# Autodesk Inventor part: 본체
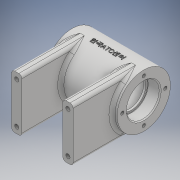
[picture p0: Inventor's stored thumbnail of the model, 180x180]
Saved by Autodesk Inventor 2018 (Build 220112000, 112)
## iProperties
Created: 2020-07
Part Number: 본체
Material: Generic
Document SubType Name: Modeling
Designer: Administrator
Density: 1 g/cm^3
Appearance: Default
Author: Administrator
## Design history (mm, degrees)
sketch "Sketch1"
  geometry: L1 (0, 26)-(-35, 26); L2 (0, 26)-(35, 26); L3 (-35, 26)-(-35, 16); L4 (-35, 16)-(-23.3, 16); L5 (-23, 15.7)-(-23, 14); L6 (-23, 14)-(-21, 14); L7 (-21, 14)-(-21, 18); L8 (-18, 21)-(18, 21); L9 (21, 18)-(21, 14); L10 (21, 14)-(23, 14); L11 (23, 14)-(23, 15.7); L12 (23.3, 16)-(35, 16); L13 (35, 16)-(35, 26); L14 (-35, 0)-(35, 0); A1 r 0.3 centre (-23.3, 15.7) between (-23, 15.7) and (-23.3, 16); A2 r 0.3 centre (23.3, 15.7) between (23.3, 16) and (23, 15.7); A3 r 3 centre (18, 18) between (21, 18) and (18, 21); A4 r 3 centre (-18, 18) between (-18, 21) and (-21, 18); 5 further points
  constraints: 28 end point, 9 perpendicular, 8 point on circle, 8 point on line, 8 tangent, 4 centre point, 2 equal radius, 2 horizontal, 2 vertical
  dimensions: "d1" = 35 distance of L1.start L1.end; "d2" = 35 distance of L1.start L2.end; "d3" = 10 distance of L1.end L3.end; "d4" = 12 distance of L3.end point (-23, 16); "d5" = 2 distance of point (-23, 16) L5.end; "d6" = 2 distance of L5.end L6.end; "d7" = 7 distance of L6.end point (-21, 21); "d8" = 42 distance of point (-21, 21) point (21, 21); "d9" = 7 distance of point (21, 21) L9.end; "d10" = 2 distance of L9.end L10.end; "d11" = 2 distance of L10.end point (23, 16); "d12" = 12 distance of point (23, 16) L12.end; "d13" = 0.3 radius of A1; "d14" = 3 radius of A3
revolve "Revolution1" sketch "Sketch1" stored, may be unused: angle "d15" = 90 deg
sketch "Sketch2"
  geometry: L1 (0, 23.558)-(0, 29); L2 (0, 29)-(5, 29); L3 (0, 23.558)-(5, 23.558); L4 (5, 23.558)-(5, 29); 1 further point
  constraints: 8 end point, 2 horizontal, 1 perpendicular, 1 vertical
  dimensions: "d18" = 5.442 distance of L1.start L1.end; "d19" = 5 distance of L1.end L2.end
revolve "Revolution2" sketch "Sketch2" stored, may be unused: angle "d20" = 90 deg
sketch "Sketch3"
  geometry: 2 further points
  constraints: 1 coincident
hole "Hole1" sketch "Sketch3" at (0, 0) diameter "d21" = 5.188; stored, may be unused: countersink angle "d25" = 90 deg, drill point angle "d27" = 118 deg; dims "d22" = 16, "d23" = 4, "d24" = 2, "d26" = 16
fillet "Fillet1" dims "d28" = 2
sketch "Sketch4"
  geometry: L1 (0, 0)-(-56.537, -20.578); L2 (0, 0)-(-32.45, 0); L3 (-21.871, -7.961)-(-19.819, -13.599); L4 (-19.819, -13.599)-(-25.199, -15.557); L5 (-25.199, -15.557)-(-27.251, -9.919); C1 r 26 at (0, 0) reference
  constraints: 10 end point, 2 perpendicular, 2 point on line, 1 horizontal, 1 parallel
  dimensions: "d31" = 20 deg angle of L2 L1; "d32" = 29 distance from line of L1.start L5; "d33" = 12 diameter of L4 L1; "d34" = 5.72494 distance between parallel lines of L3 L5; "d35" = 17.09868 distance from line of L2.end L4; "d36" = 20.57767 distance from line of L1.end L2
revolve "Revolution3" sketch "Sketch4" stored, may be unused: angle "d37" = 90 deg
sketch "Sketch5"
  geometry: 2 further points
  constraints: 1 coincident
hole "Hole2" sketch "Sketch5" at (0, 0) diameter "d38" = 5.188; stored, may be unused: countersink angle "d42" = 90 deg, drill point angle "d44" = 118 deg; dims "d39" = 16, "d40" = 4, "d41" = 2, "d43" = 16
fillet "Fillet2" dims "d45" = 2
workplane "Work Plane1"
sketch "Sketch6"
  geometry: L1 (0, 26)-(-64, 26); L2 (0, -26)-(-64, -26); L3 (-64, 26)-(-64, -26); A1 r 26 centre (0, 0) between (0, 26) and (0, -26) reference; 1 further point
  constraints: 6 end point, 2 horizontal, 2 point on circle, 2 tangent
  dimensions: "d49" = 64 distance of L1.start L1.end; "d50" = 64 distance of L2.start L2.end
extrude "Extrusion1" join sketch "Sketch6" stored distance "d51" = 10; taper "d52" = 0 deg
mirror "Mirror1"
fillet "Fillet3" dims "d53" = 3
sketch "Sketch7"
  geometry: 5 further points
hole "Hole3" sketch "Sketch7" at (0, 21), (-21, 0), (0, -21), (21, 0) diameter "d55" = 3.242; stored, may be unused: countersink angle "d59" = 90 deg, drill point angle "d61" = 118 deg; dims "d56" = 8, "d57" = 4, "d58" = 2, "d60" = 10
mirror "Mirror2"
sketch "Sketch8"
  geometry: L1 (-3, 49)-(-3, 3) reference; L2 (47, 49)-(47, 3) reference; 5 further points
hole "Hole4" sketch "Sketch8" at (2, 46), (2, 6), (52, 46), (52, 6) diameter "d68" = 4.134; stored, may be unused: countersink angle "d72" = 90 deg, drill point angle "d74" = 118 deg; dims "d69" = 8, "d70" = 4, "d71" = 2, "d73" = 10
workplane "Work Plane2"
sketch "Sketch9"
  geometry: L1 (35, -26)-(35, 26) reference; L2 (-35, -26)-(-35, 26) reference; 2 further points
  constraints: 1 other
  dimensions: "d76" = 35 distance from line of point (0, 0) L2 (derived); "d77" = 26 vertical distance of point (0, 0) L2.end (derived)
emboss "Emboss1" sketch "Sketch9" dims "d1" = 35, "d2" = 35, "d3" = 10, "d4" = 12, "d5" = 2, "d6" = 2, "d7" = 7, "d8" = 42, "d9" = 7, "d10" = 2, "d11" = 2, "d12" = 12, "d13" = 0.3, "d14" = 3, "d78" = 0.5, "d79" = 0
chamfer "Chamfer1" distance "d80" = 1; stored, may be unused: second distance "d81" = 2, angle "d82" = 45 deg
chamfer "Chamfer2" distance "d83" = 1; stored, may be unused: second distance "d84" = 2, angle "d85" = 45 deg
body "Solid1"
other parameters: "d46" = 25, "d75" = 26
